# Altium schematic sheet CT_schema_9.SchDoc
size 226 x 144 mm
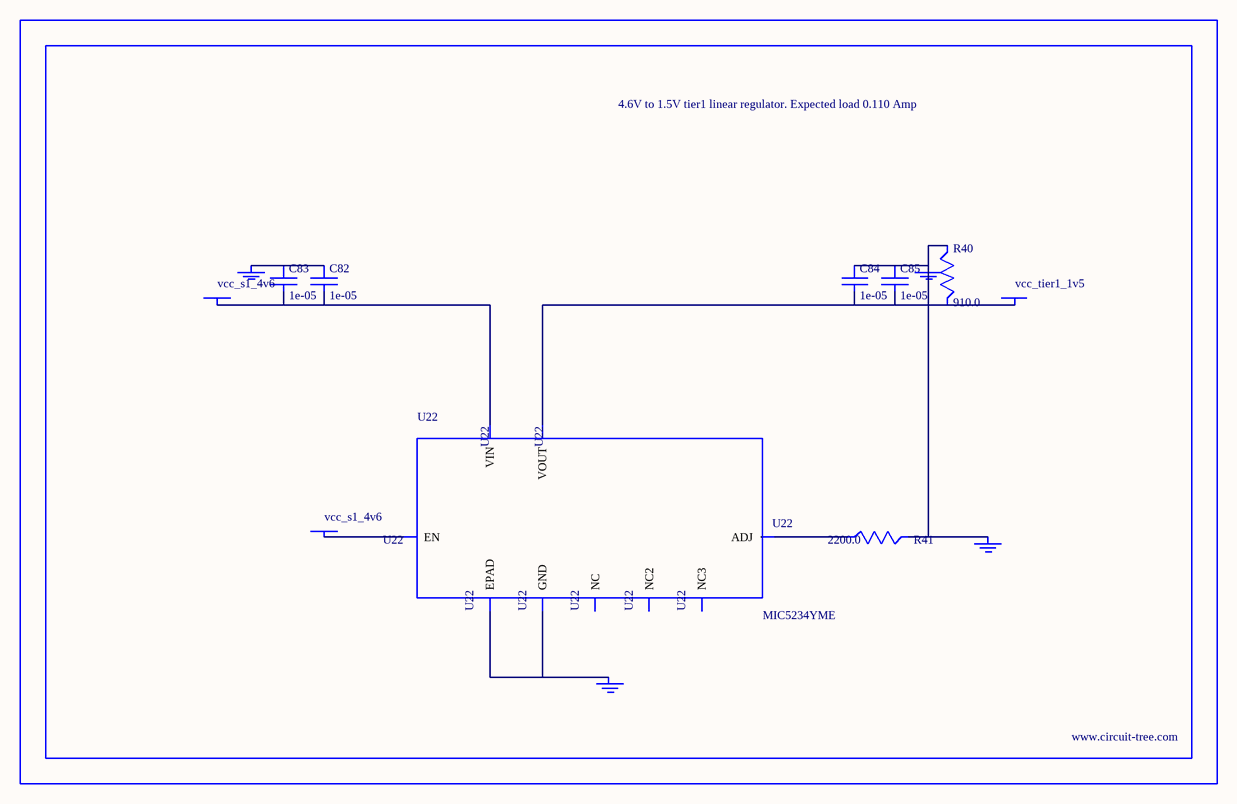
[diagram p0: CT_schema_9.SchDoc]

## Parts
BORDER8  (no value)
C82  1e-05  [C1210]
C83  1e-05  [C1210]
C84  1e-05  [C1210]
C85  1e-05  [C1210]
GND_INSTANCE_8_0  (no value)
GND_INSTANCE_8_1  (no value)
GND_INSTANCE_8_2  (no value)
GND_INSTANCE_8_3  (no value)
POWER_INSTANCE_8_0  vcc_tier1_1v5
POWER_INSTANCE_8_1  vcc_s1_4v6
POWER_INSTANCE_8_2  vcc_s1_4v6
R40  910.0  [R0603]
R41  2200.0  [R0603]
U22  MIC5234YME  [SOIC-8_EP]

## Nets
NetC82_1: C82.1 C83.1 GND_INSTANCE_8_3.0(GND)
NetC82_2: C82.2 C83.2 POWER_INSTANCE_8_2.0(PWR) U22.8(VIN)
NetC84_1: C84.1 C85.1 GND_INSTANCE_8_0.0(GND) GND_INSTANCE_8_1.0(GND) R40.1 R41.2
NetC84_2: C84.2 C85.2 POWER_INSTANCE_8_0.0(PWR) R40.2 U22.1(VOUT)
NetGND_INSTANCE_8_2_0: GND_INSTANCE_8_2.0(GND) U22.7(GND) U22.EPAD
NetPOWER_INSTANCE_8_1_0: POWER_INSTANCE_8_1.0(PWR) U22.5(EN)
NetR41_1: R41.1 U22.4(ADJ)

Not connected (* = marked no-connect by the designer): U22 2(NC) 3(NC2) 6(NC3)

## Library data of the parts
BORDER8 = BORDER_PAGE8
C82-C85 = C1210C106K5PACTU
GND_INSTANCE_8_0-GND_INSTANCE_8_3 = GND
POWER_INSTANCE_8_0-POWER_INSTANCE_8_2 = PWR
R40 = RC0603JR-07910RL
R41 = RC0603JR-072K2L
